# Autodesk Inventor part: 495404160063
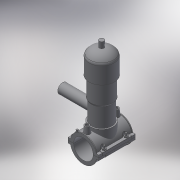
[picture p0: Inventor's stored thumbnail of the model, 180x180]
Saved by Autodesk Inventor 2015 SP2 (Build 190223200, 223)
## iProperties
Created: 2017-07
Part Number: 495404160063
Material: Generic
Description: PLASSON TAPPING VALVE 160-63
Document SubType Name: Modeling
Designer: KIM
Density: 1 g/cm^3
Appearance: Default
Author: KIM
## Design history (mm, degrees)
derived "495404-4954S4.ipt"
feature "Solid1::495404-4954S4.ipt"
feature "Solid2::495404-4954S4.ipt"
tag "TaggingFeature1"
body "Solid1"
body "Solid2"
other parameters: "d2" = 202, "d4" = 118, "d5" = 0, "d6" = 0.1, "d8" = 0, "d19" = 6, "d20" = 6, "d21" = 70.8, "d23" = 0, "d24" = 35.4, "d26" = 0, "d27" = 3, "d28" = 3, "d29" = 3, "d30" = 53.33333, "d31" = 6, "d32" = 0, "d33" = 0, "d34" = 0.6, "d40" = 99.84, "d47" = 147, "d70" = 15, "d72" = 0, "d73" = 6, "d75" = 5, "d76" = 0, "d77" = 8, "d79" = 15, "d80" = 47.2, "d82" = 5 deg, "d84" = 4, "d85" = 14, "d86" = 0, "d87" = 3, "d88" = 0, "d89" = 1, "d90" = 1, "d91" = 94.4, "d92" = 0, "d93" = 0.5, "d94" = 84.21053, "d96" = 197.76, "d97" = 2.36, "d98" = 0, "d120" = 140 deg, "d121" = 24.228, "d122" = 20 deg, "d123" = 384, "d124" = 115.2, "d126" = 0, "d143" = 164.8, "d145" = 24.61538, "d149" = 2.4, "d150" = 27.07692, "d153" = 118, "d154" = 0, "d156" = 96, "d157" = 160 deg, "d159" = 6.4, "d161" = 2.4, "d162" = 70.8, "d163" = 0, "d167" = 16, "d168" = 93.65854, "d170" = 3, "d172" = 0, "d173" = 1, "d176" = 20 deg, "d177" = 11.2, "d178" = 32, "d180" = 0, "d183" = 12.8, "d184" = 8.96, "d185" = 38.35, "d186" = 38.35, "d187" = 96, "d188" = 9.6, "d189" = 11.2, "d190" = 0, "d191" = 144, "d193" = 6.8, "d194" = 2.95, "d195" = 90 deg, "d197" = 0, "d199" = 0, "d205" = 14.64, "d206" = 81.33333, "d207" = 244, "d208" = 224.48, "d209" = 207.4, "d210" = 200.08, "d211" = 146.4, "d212" = 85.4, "d213" = 65.88, "d214" = 73.2, "d216" = 19.52, "d217" = 70.76, "d218" = 80.52, "d222" = 0, "d223" = 192, "d224" = 186, "d225" = 51, "d226" = 63, "d229" = 186, "d230" = 0, "B_" = 202, "H_" = 186, "L_" = 118, "d_t" = 6, "d_1" = 63, "H_1" = 51, "H_2" = 244, "d148" = 2.4, "d160" = 2.4, "d169" = 3, "d192" = 6.8, "d228" = 50.4
